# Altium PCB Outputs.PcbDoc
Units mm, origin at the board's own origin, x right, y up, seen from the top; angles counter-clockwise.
Board outline 53 x 31.5 mm, 2 copper layers (Top Layer, Bottom Layer); 7 components, 4 nets, 16 pads, 0 vias.
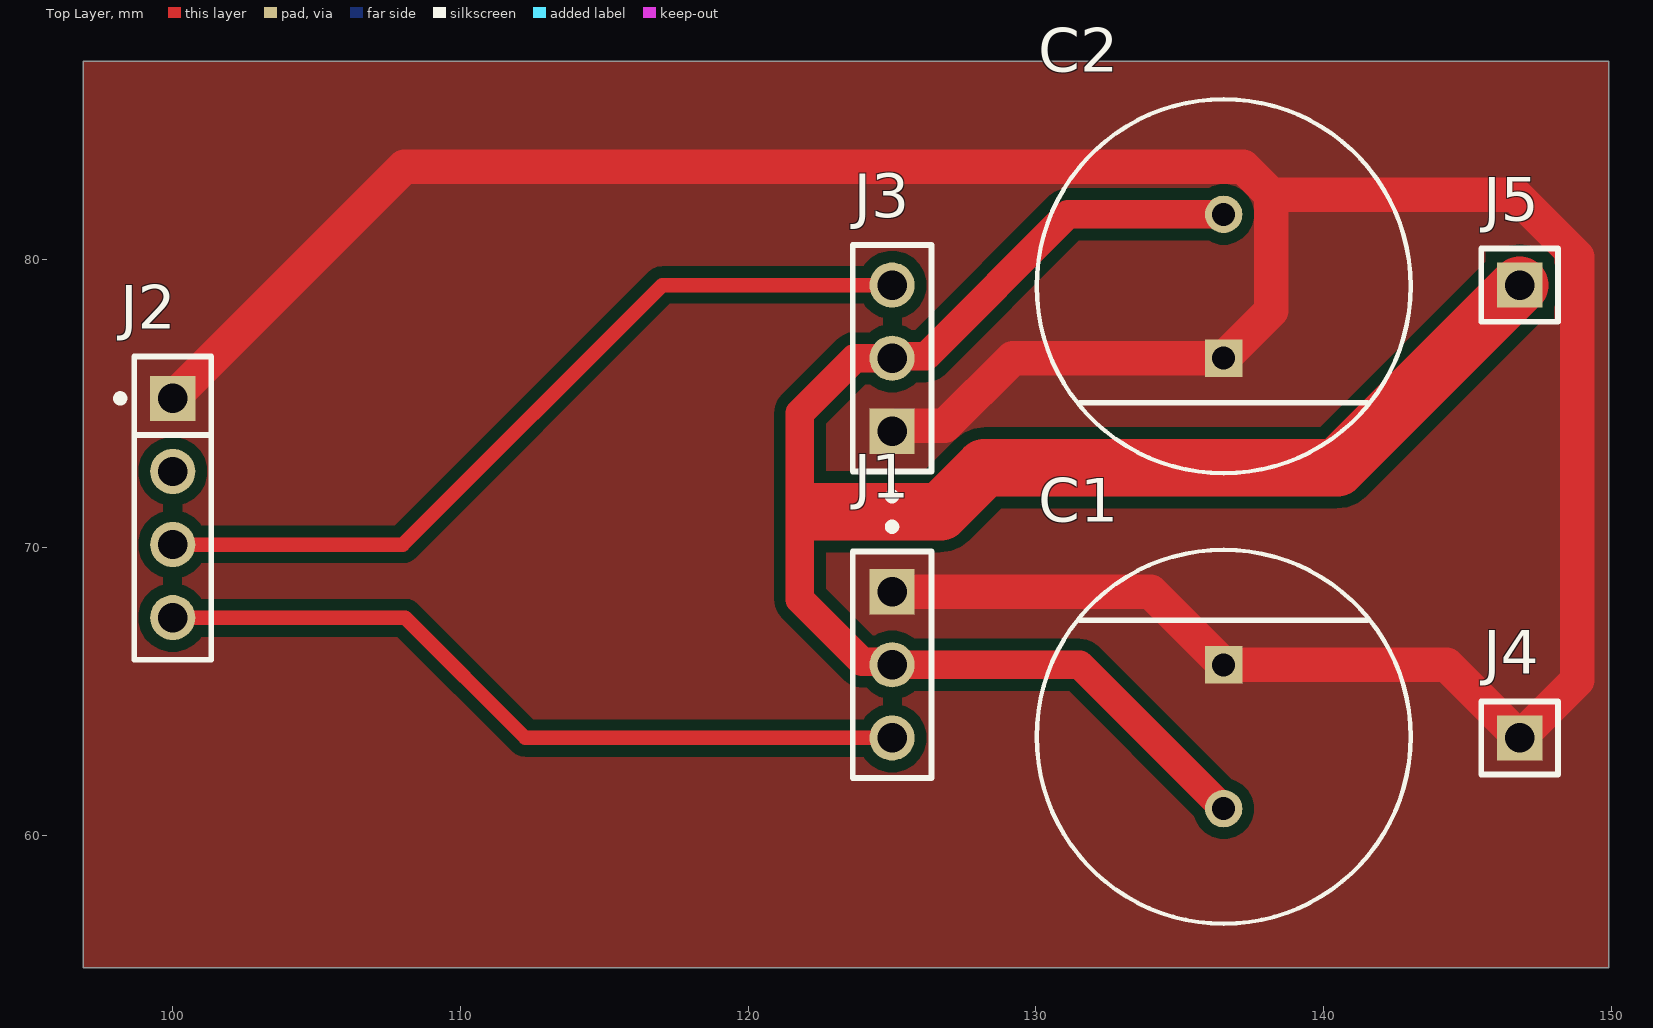
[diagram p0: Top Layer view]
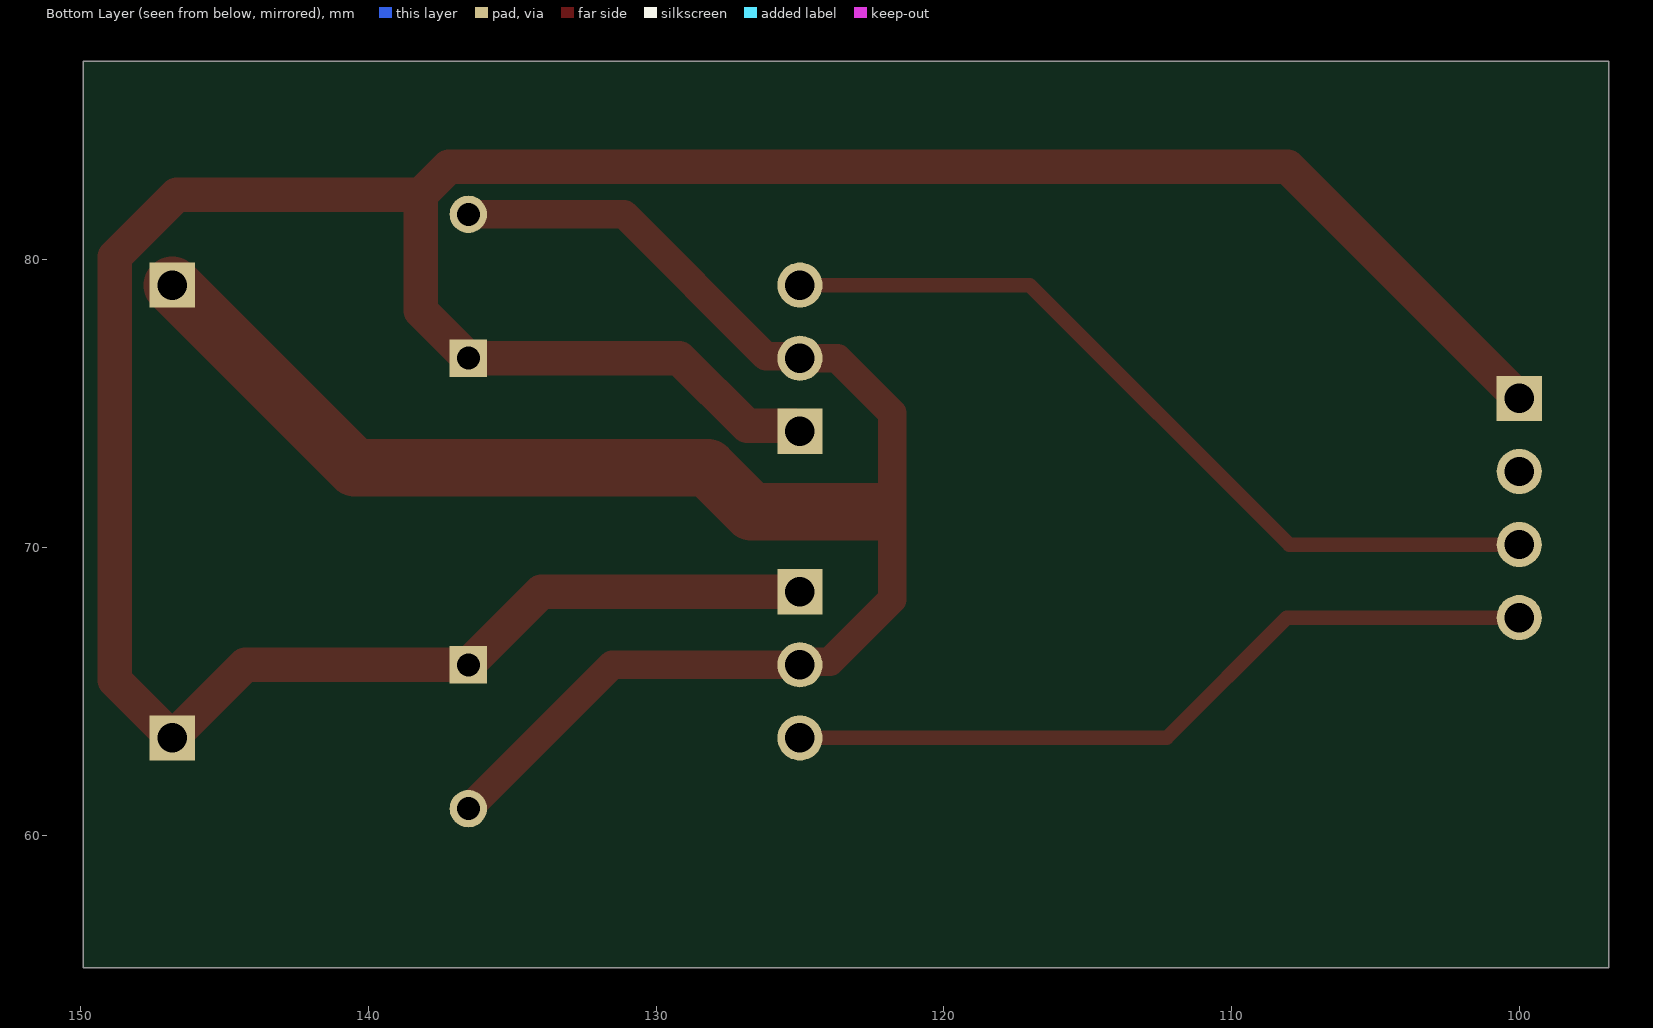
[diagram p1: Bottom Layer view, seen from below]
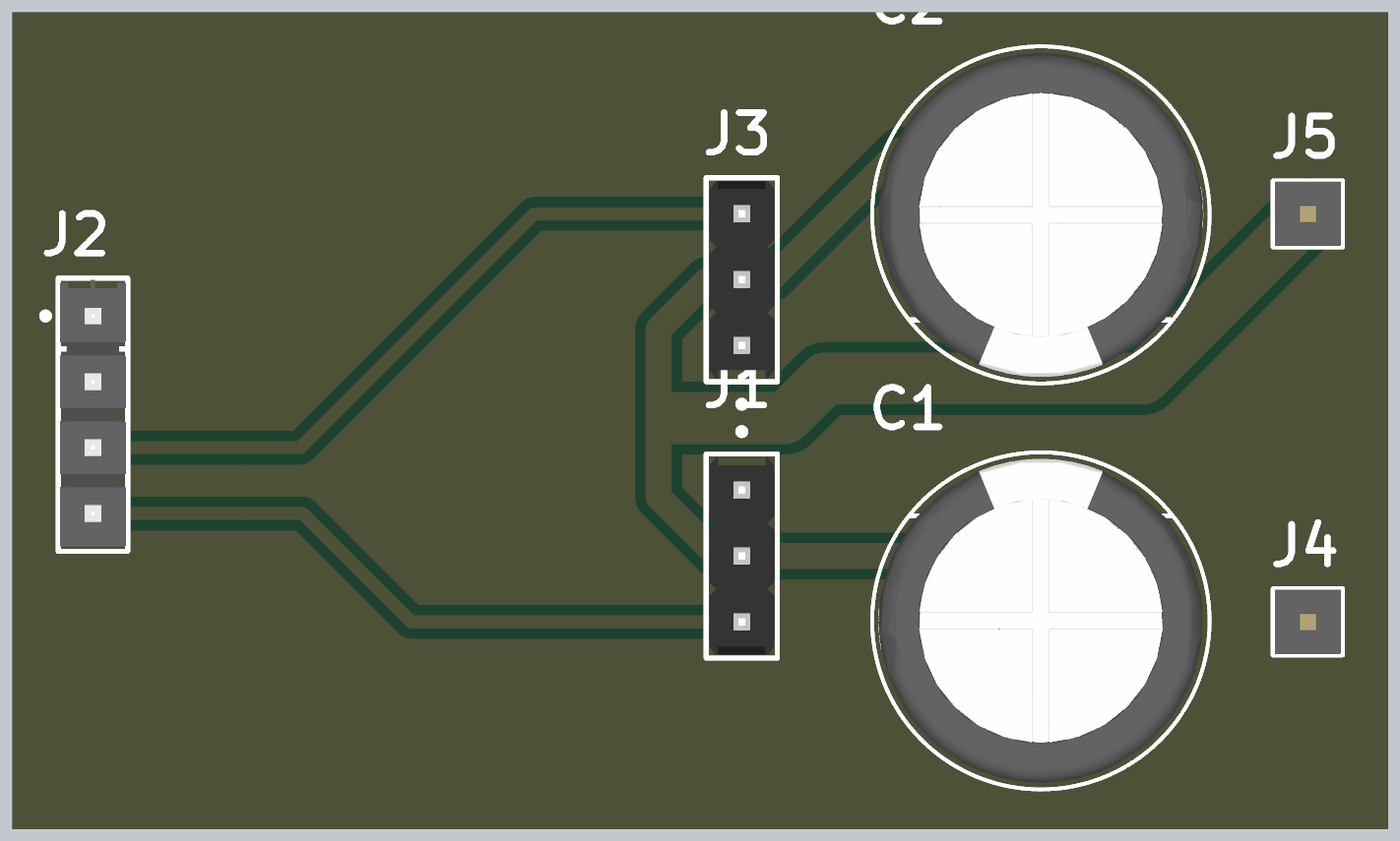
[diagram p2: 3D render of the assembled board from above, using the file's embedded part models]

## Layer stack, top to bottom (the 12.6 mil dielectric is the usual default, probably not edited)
Top Solder: solder mask 0.0102, Solder Resist, Dk 3.5
Top Layer: signal copper 0.0356
Dielectric 1: dielectric 0.32, FR-4, Dk 4.8
Bottom Layer: signal copper 0.0356
Bottom Solder: solder mask 0.0102, Solder Resist, Dk 3.5

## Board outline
96.899,55.392 96.899,86.892 149.899,86.892 149.899,55.392

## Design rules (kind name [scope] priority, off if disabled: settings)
Clearance [All] p1: gap=0.4 ignorepadtopadclearanceinfootprint=FALSE
PolygonConnect [All] p1: connectstyle=Direct reliefconductorwidth=0.5 reliefentries=4 polygonreliefangle="90 Angle" airgapwidth=0.4
RoutingVias [All] p1: holewidth=0.711 width=1.27 viastyle="Through Hole" minholewidth=0.711 minwidth=1.27 maxholewidth=0.711 maxwidth=1.27
SolderMaskExpansion [All] p1: expansion=0 istentingtop=FALSE
SupplyNets "Schematic Supply Nets_1" [InNet('+5')] p1: voltage=0.000
SupplyNets "Schematic Supply Nets" [InNet('GND')] p2: voltage=0.000
Width [All] p1: maxlimit=2 minlimit=0.254 preferedwidth=1.2 minimp=50.000000 maximp=50.000000 favimp=50.000000
30 further rules are at their usual default settings.

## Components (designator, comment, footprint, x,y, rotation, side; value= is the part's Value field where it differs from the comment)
C1 "EEUFC1H471B" FP-RAD-TH-D_12_5_0_5-L_25-MFG 136.525,63.424 r270 top
C2 "EEUFC1H471B" FP-RAD-TH-D_12_5_0_5-L_25-MFG 136.525,79.081 r90 top
J1 "" FP-22-28-4030-MFG 125,65.924 r270 top
J2 "I2C" FP-TSW-104-23-T-S-MFG 100,71.374 r270 top
J3 "" FP-22-28-4030-MFG 125,76.581 r90 top
J4 "" FP-HTSW-101-07-L-S-MFG 146.812,63.384 r180 top
J5 "" FP-HTSW-101-07-L-S-MFG 146.812,79.121 r0 top

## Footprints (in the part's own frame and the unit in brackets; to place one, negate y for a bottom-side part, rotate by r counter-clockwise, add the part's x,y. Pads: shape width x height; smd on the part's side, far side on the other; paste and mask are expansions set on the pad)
FP-22-28-4030-MFG [mm]
  rect 1.57x1.57 hole 1.02 paste-2539.97 mask+0: 1(-2.54,0)
  round 1.57 hole 1.02 paste-2539.97 mask+0: 2(0,0) 3(2.54,0)
  silkscreen extent -4.92,-1.37 3.94,1.37, body extent -4.04,-1.47 4.04,1.47, height 0.25
FP-HTSW-101-07-L-S-MFG [mm]
  rect 1.57x1.57 hole 1.02 paste-2539.97 mask+0: 1(0,0)
  silkscreen extent -1.33,-1.27 1.33,1.27, body extent -1.43,-1.37 1.43,1.37, height 0.25
FP-RAD-TH-D_12_5_0_5-L_25-MFG [mm]
  rect 1.3x1.3 hole 0.8 paste-2539.97 mask+0: 1(-2.5,0)
  round 1.3 hole 0.8 paste-2539.97 mask+0: 2(2.5,0)
  silkscreen extent -6.5,-6.5 6.5,6.5, body extent -6.6,-6.6 6.6,6.6, height 0.25
FP-TSW-104-23-T-S-MFG [mm]
  rect 1.57x1.57 hole 1.02 paste-2539.97 mask+0: 1(-3.81,0)
  round 1.57 hole 1.02 paste-2539.97 mask+0: 2(-1.27,0) 3(1.27,0) 4(3.81,0)
  silkscreen extent -5.27,-1.95 5.27,1.34, body extent -5.37,-1.44 5.37,1.44, height 0.25

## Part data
C1 C2: library part CMP-05427-000674-1, "Aluminum Electrolytic Capacitors (Radial Lead Type) AEC-Q200 Qualified 470uF ±20% 50V", Capacitance=470uF, Case/Package=Radial, Dielectric Material=Aluminium, ESR (Equivalent Series Resistance)=50mR, Leakage Current=3uA, Max Operating Temperature=105°C, Min Operating Temperature=-55°C, Package Quantity=500, Ripple Current=1.832A, Tolerance=20%, Voltage=50V
J1 J3: library part CMP-04776-000098-1, "CONN HEADER VERT 3POS 2.54MM", Current Rating=4A, Manufacturer=Molex, Manufacturer Part Number=22-28-4030, Temperature="-40°C to +80°C", Temperature Range High=+80°C, Temperature Range Low=-40°C, Voltage Rating=500V
J2: library part CMP-02766-001388-1, "CONN HEADER VERT 4POS 2.54MM", Color=Black, Max Current Rating=7.6A, Max Operating Temperature=105°C, Max Voltage Rating (AC)=550V, Min Operating Temperature=-55°C, Package Quantity=1
J4 J5: library part CMP-02766-001464-1, "CONN HEADER VERT 1POS", Housing Color=Natural, Max Current Rating=7.6A, Max Operating Temperature=125°C, Max Voltage Rating (AC)=550V, Min Operating Temperature=-55°C

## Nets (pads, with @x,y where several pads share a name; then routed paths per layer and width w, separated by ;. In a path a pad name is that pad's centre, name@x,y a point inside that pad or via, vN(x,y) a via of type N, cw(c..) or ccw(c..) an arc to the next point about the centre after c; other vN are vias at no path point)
+5: C1.2 C2.2 J1.2 J3.2 J5.1 | length 69.7
  Top Layer w1: J1.2@124.9,65.924 J1.2 ; J3.2 123.698,76.581 121.793,74.676 121.793,68.199 123.959,66.033 124.891,66.033 J1.2 ; J3.2@125.071,76.652 126.182,76.652 131.111,81.581 C2.2 ; C1.2 131.525,65.924 J1.2
  Top Layer w1.2: J3.2 J3.2@125.071,76.652
  Top Layer w2: 122.301,71.247 126.682,71.247 128.206,72.771 140.462,72.771 J5.1
D9: J1.3 J2.4 | length 26.7
  Top Layer w0.5: J2.4 108.077,67.564 112.257,63.384 J1.3
D10: J2.3 J3.3 | length 28.7
  Top Layer w0.5: J2.3 107.992,70.104 117.009,79.121 J3.3
GND: C1.1 C2.1 J1.1 J2.1 J3.1 J4.1 | length 113.8
  Top Layer w1.2: J2.1 108.047,83.231 137.208,83.231 138.175,82.264 ; J1.1 133.985,68.464 C1.1 144.272,65.924 J4.1 148.812,65.384 148.812,80.105 146.653,82.264 138.175,82.264 ; J3.1 125.185,74.226 126.833,74.226 129.188,76.581 C2.1 138.175,78.231 138.175,82.264
pads on no net: J2.2

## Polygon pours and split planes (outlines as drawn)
GND on Top Layer (solid, pour order 0): 96.899,55.392 96.899,86.892 149.899,86.892 149.899,55.392

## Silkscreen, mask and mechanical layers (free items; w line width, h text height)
Mechanical 1:
  the board outline again, w1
